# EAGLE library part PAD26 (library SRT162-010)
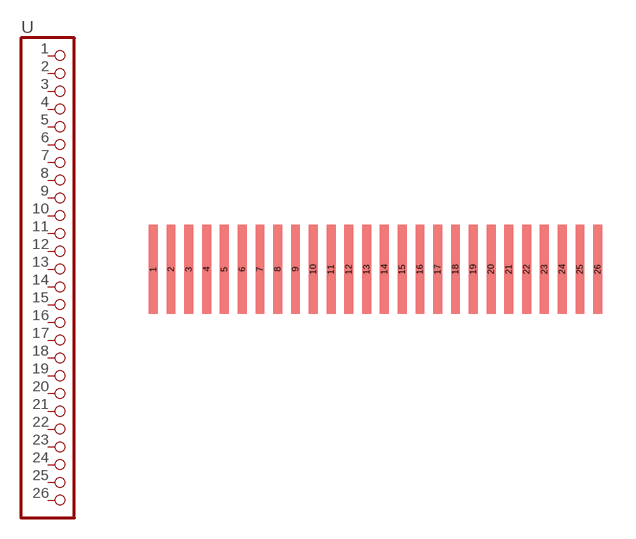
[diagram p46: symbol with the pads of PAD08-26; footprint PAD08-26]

Designator prefix -

## PAD2608  [PAD08-26]
1  1  pas
2  2  pas
3  3  pas
4  4  pas
5  5  pas
6  6  pas
7  7  pas
8  8  pas
9  9  pas
10  10  pas
11  11  pas
12  12  pas
13  13  pas
14  14  pas
15  15  pas
16  16  pas
17  17  pas
18  18  pas
19  19  pas
20  20  pas
21  21  pas
22  22  pas
23  23  pas
24  24  pas
25  25  pas
26  26  pas

## Footprint PAD08-26 (pad centres in mm)
smd 0.4 x 4: 1 -10.4,0; 2 -9.6,0; 3 -8.8,0; 4 -8,0; 5 -7.2,0; 6 -6.4,0; 7 -5.6,0; 8 -4.8,0; 9 -4,0; 10 -3.2,0; 11 -2.4,0; 12 -1.6,0; 13 -0.8,0; 14 0,0; 15 0.8,0; 16 1.6,0; 17 2.4,0; 18 3.2,0; 19 4,0; 20 4.8,0; 21 5.6,0; 22 6.4,0; 23 7.2,0; 24 8,0; 25 8.8,0; 26 9.6,0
